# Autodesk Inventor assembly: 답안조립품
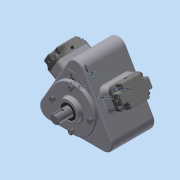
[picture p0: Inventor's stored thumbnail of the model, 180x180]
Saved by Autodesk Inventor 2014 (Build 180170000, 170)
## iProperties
Created: 2015-06
Part Number: 답안조립품
Document SubType Name: Assembly
Designer: MYHOME
Mass: 5318.58 g
Surface Area: 2414.93 cm^2
Volume: 1564.62 cm^3
Density: 3.39928 g/cm^3
Author: MYHOME
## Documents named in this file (20)
- C:\Documents and Settings\MYHOME\바탕 화면\350605V1047\답안조립품.iam
- C:\Documents and Settings\MYHOME\바탕 화면\350605V1047\본체.ipt
- C:\Documents and Settings\MYHOME\바탕 화면\350605V1047\베어링 NA 4904.ipt
- 베어링 NA 4904.ipt
- C:\Documents and Settings\MYHOME\바탕 화면\350605V1047\편심축.ipt
- C:\Documents and Settings\MYHOME\바탕 화면\350605V1047\앞커버.ipt
- C:\Documents and Settings\MYHOME\바탕 화면\350605V1047\오일실.ipt
- 오일실.ipt
- C:\Documents and Settings\MYHOME\바탕 화면\350605V1047\M6x0.7x20.ipt
- M6x0.7x20.ipt
- C:\Documents and Settings\MYHOME\바탕 화면\350605V1047\부시.ipt
- C:\Documents and Settings\MYHOME\바탕 화면\350605V1047\헤더커버.ipt
- 헤더커버.ipt
- C:\Documents and Settings\MYHOME\바탕 화면\350605V1047\M4x0.5x16.ipt
- M4x0.5x16.ipt
- C:\Documents and Settings\MYHOME\바탕 화면\350605V1047\슬라이드.ipt
- C:\Documents and Settings\MYHOME\바탕 화면\350605V1047\9-스프링.ipt
- C:\Documents and Settings\MYHOME\바탕 화면\350605V1047\8-스프링.ipt
- C:\Documents and Settings\MYHOME\바탕 화면\350605V1047\11-스프링.ipt
- C:\Documents and Settings\MYHOME\바탕 화면\350605V1047\10-스프링.ipt
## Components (18 placed, 7 different names)
1. 헤더커버:1
2. M4x0.5x16:1
3. M4x0.5x16:2
4. M4x0.5x16:3
5. M4x0.5x16:4
6. 헤더커버:2
7. M4x0.5x16:5
8. M4x0.5x16:6
9. M4x0.5x16:7
10. M4x0.5x16:8
11. 9-스프링:1
12. 8-스프링:1
13. 11-스프링:1
14. 10-스프링:1
15. M6x0.7x20:1
16. M6x0.7x20:2
17. M6x0.7x20:3
18. M6x0.7x20:4
